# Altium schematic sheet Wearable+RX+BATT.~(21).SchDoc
size A2; PageSetup: Record=PageOptions|CenterHorizontal=True|CenterVertical=True|PrintScale=0.71|XCorrection=1.00|YCorrection=1.00|PrintKind=2|BorderSize=5000000|LeftOffset=0|BottomOffset=0|Orientation=2|PaperLength=1000|PaperWidth=1000|Scale=100|PaperSource=7|PrintQuality=-4|MediaType=1|DitherType=10|PaperKind=A3|PrintScaleMode=1
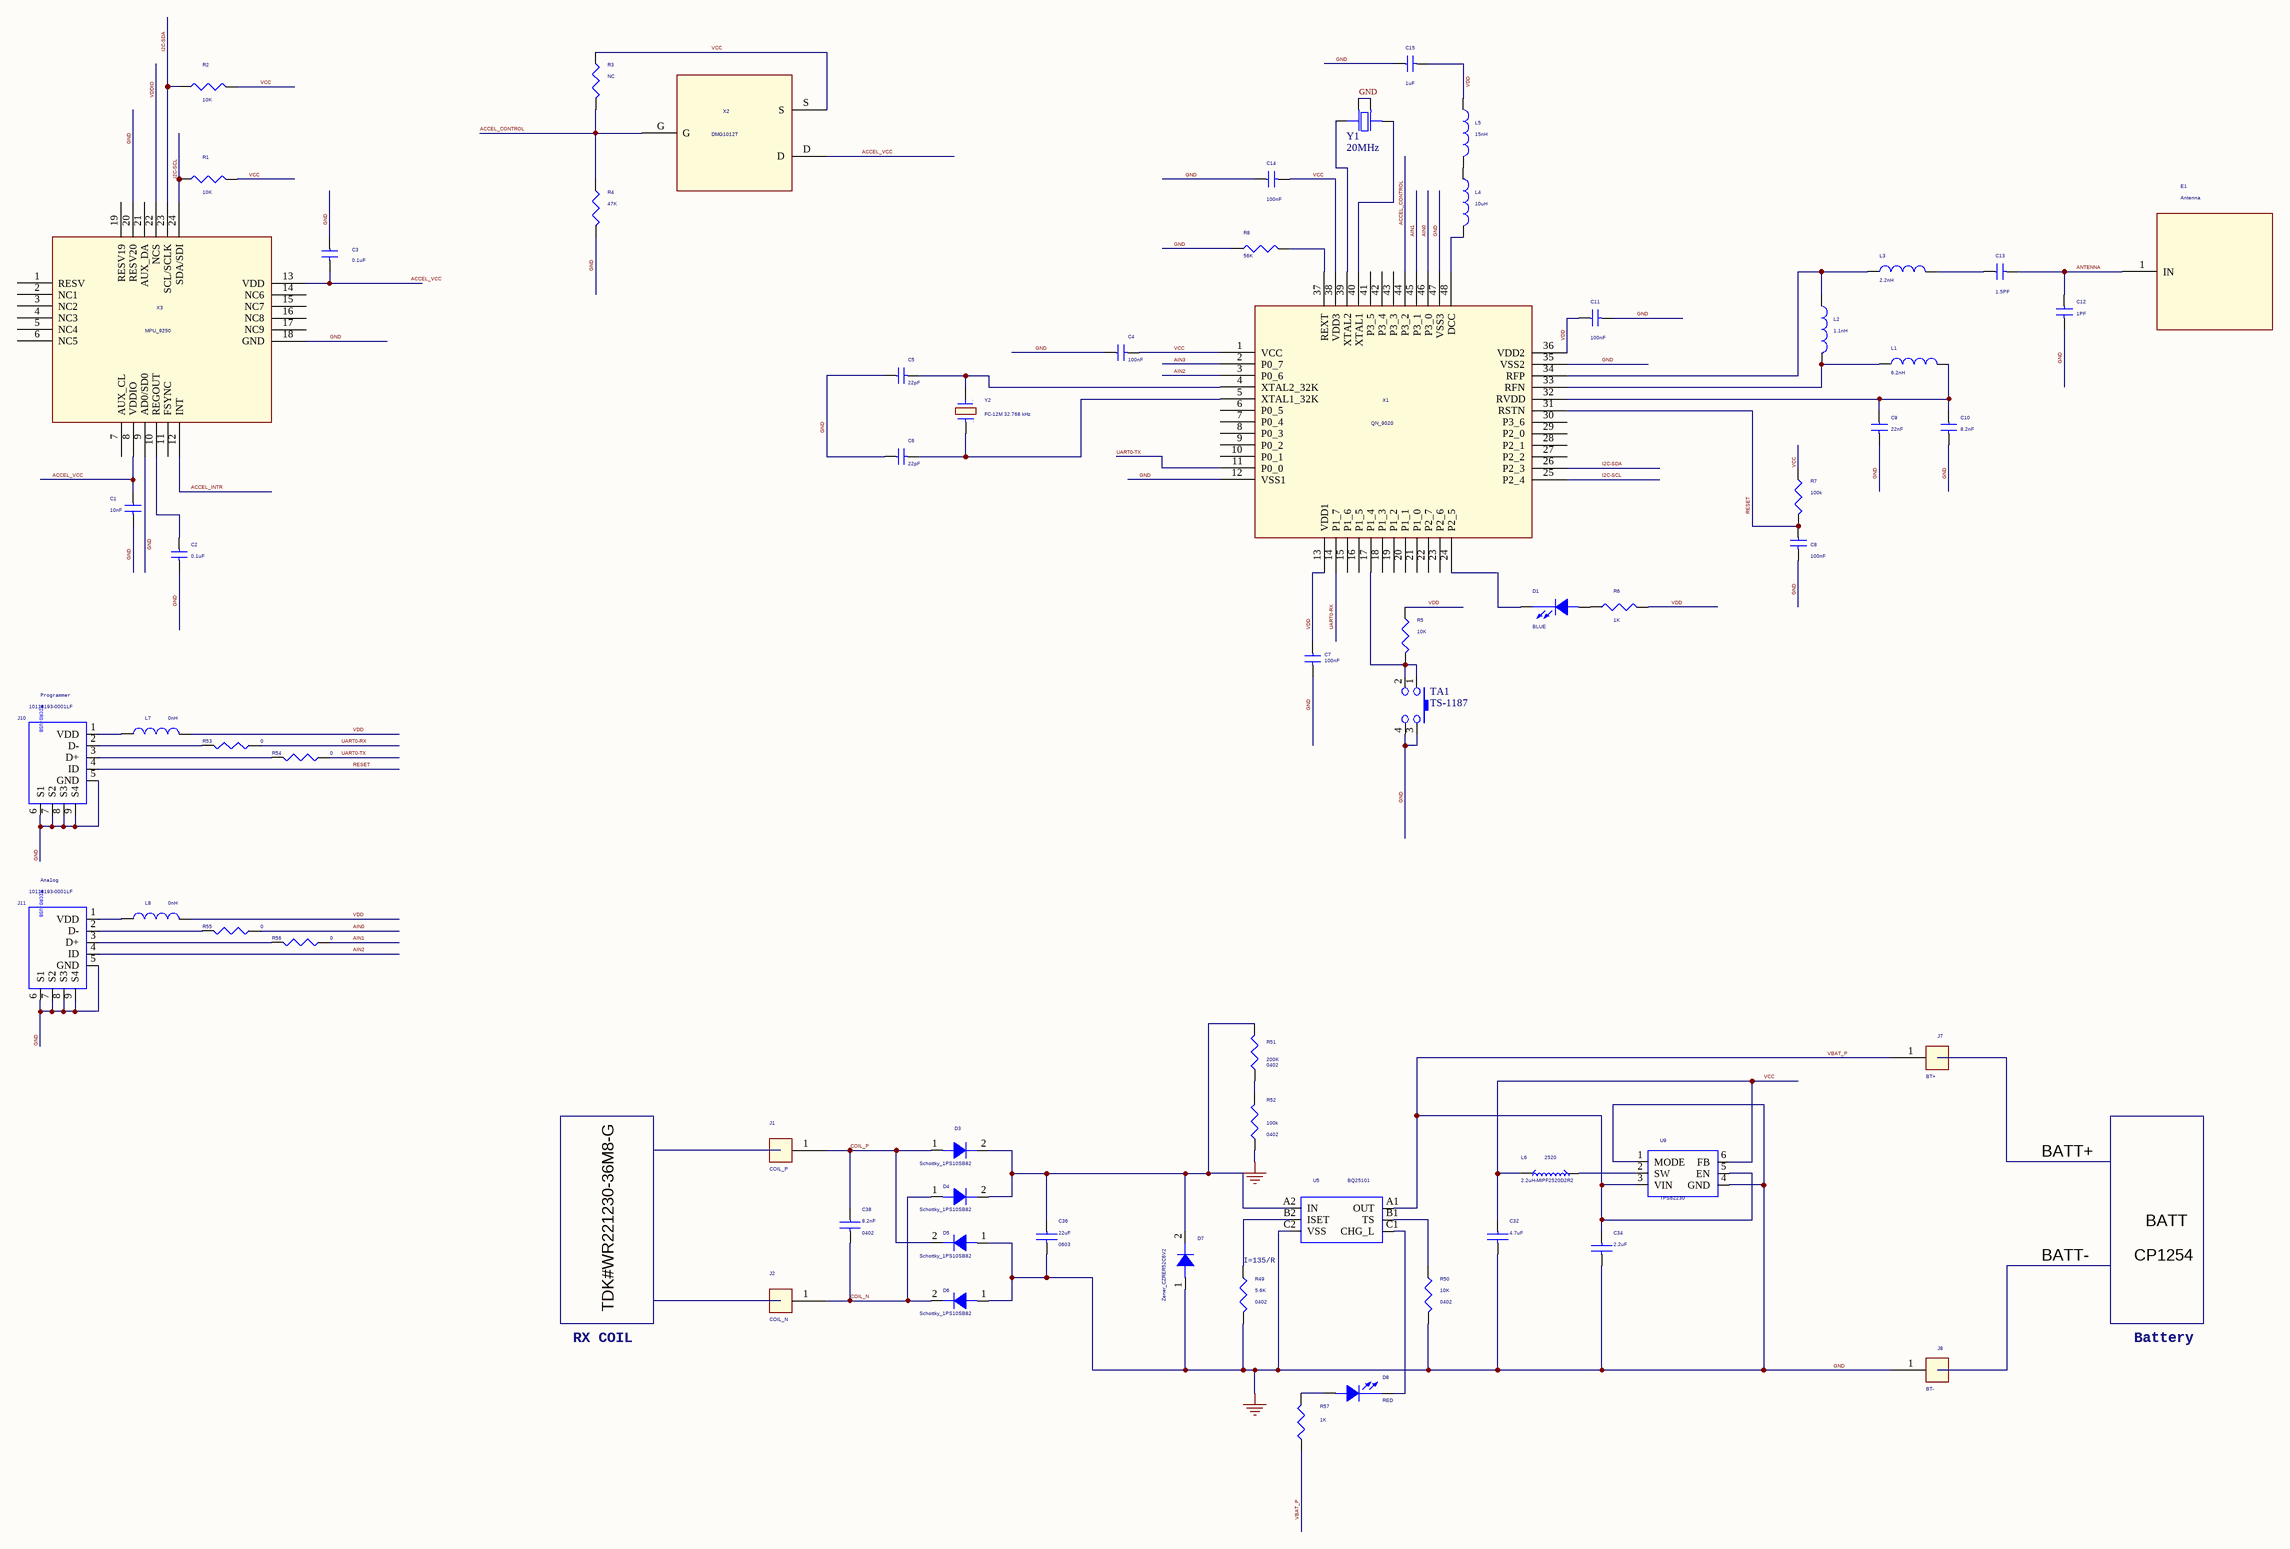
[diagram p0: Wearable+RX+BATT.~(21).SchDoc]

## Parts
C1  10nF  [0402C]
C2  0.1uF  [0402C]
C3  0.1uF  [0402C]
C4  100nF  [0402C]
C5  22pF  [0402C]
C6  22pF  [0402C]
C7  100nF  [0402C]
C8  100nF  [0402C]
C9  22nF  [0402C]
C10  8.2nF  [0402C]
C11  100nF  [0402C]
C12  1PF  [0402C]
C13  1.5PF  [0402C]
C14  100nF  [0402C]
C15  1uF  [0402C]
C32  4.7uF  [0402C]
C34  2.2uF  [0402C]
C36  22uF  Package: 0603  [0603CS]
C38  8.2nF  Package: 0402  [0402C]
D1  BLUE  [0603D]
D3  Schottky_1PS10SB82  [SOD882]
D4  Schottky_1PS10SB82  [SOD882]
D5  Schottky_1PS10SB82  [SOD882]
D6  Schottky_1PS10SB82  [SOD882]
D7  Zener_CZRER52C6V2  [1308D]
D8  RED  [0603D]
E1  Antenna  [3216]
J1  COIL_P  [PAD]
J2  COIL_N  [PAD]
J7  BT+  [PAD]
J8  BT-  [PAD]
J10  10118193-0001LF  [10118193-0001LF]
J11  10118193-0001LF  [10118193-0001LF]
L1  6.2nH  [0402L]
L2  1.1nH  [0402L]
L3  2.2nH  [0402L]
L4  10uH  [0603LS]
L5  15nH  [0402L]
L6  2.2uH-MIPF2520D2R2  [2520]
L7  0nH  [0402L]
L8  0nH  [0402L]
R1  10K  [0402R]
R2  10K  [0402R]
R3  NC  [0402R]
R4  47K  [0402R]
R5  10K  [0402R]
R6  1K  [0402R]
R7  100k  [0402R]
R8  56K  [0402R]
R49  5.6K  PACKAGE: 0402  [0402R]
R50  10K  PACKAGE: 0402  [0402R]
R51  200K  PACKAGE: 0402  [0402R]
R52  100k  PACKAGE: 0402  [0402R]
R53  0  [0402R]
R54  0  [0402R]
R55  0  [0402R]
R56  0  [0402R]
R57  1K  [0402R]
TA1  TS-1187  [TS-1187]
U5  BQ25101  [XBGA-N6-BQ25101]
U9  TPS62230  [USON6-TPS62230]
X1  QN_9020  [Quad48]
X2  DMG1012T  [SOT523]
X3  MPU_9250  [QFN24-MPU9250]
Y1  20MHz  [FA-20H]
Y2  FC-12M 32.768 kHz  [FC-12M]

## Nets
GND: C1.2 C2.2 C3.1 C4.1 C5.1 C6.1 C7.2 C8.2 C9.2 C10.2 C11.2 C12.2 C14.1 C15.1 C32.2 C34.2 C36.2 D5.1(ANODE) D6.1(ANODE) D7.1(ANODE) J8.1 J10.5(GND) J10.6(S1) J10.7(S2) J10.8(S3) J10.9(S4) J11.5(GND) J11.6(S1) J11.7(S2) J11.8(S3) J11.9(S4) R4.2 R8.1 R49.2 R50.2 R52.1 TA1.3 TA1.4 U5.C2(VSS) U9.1(MODE) U9.4(GND) X1.12(VSS1) X1.35(VSS2) X1.47(VSS3) X3.9(AD0/SD0) X3.18(GND) X3.20(RESV20) Y1.2 Y1.4
ACCEL_CONTROL: R3.2 R4.1 X1.44(P3_2) X2.G
ACCEL_INTR: X3.12(INT)
ACCEL_VCC: C1.1 C3.2 X2.D X3.8(VDDIO) X3.13(VDD)
AIN0: R55.1 X1.46(P3_0)
AIN1: R56.1 X1.45(P3_1)
AIN2: J11.4(ID) X1.3(P0_6)
AIN3: X1.2(P0_7)
ANTENNA: C12.1 C13.2 E1.1(IN)
COIL_N: C38.2 D4.1(ANODE) D6.2(CATHODE) J2.1
COIL_P: C38.1 D3.1(ANODE) D5.2(CATHODE) J1.1
I2C-SCL: R1.1 X1.25(P2_4) X3.24(SDA/SDI)
I2C-SDA: R2.1 X1.26(P2_3) X3.23(SCL/SCLK)
RESET: C8.1 J10.4(ID) R7.2 X1.31(RSTN)
UART0-RX: R53.1 X1.14(P1_7)
UART0-TX: R54.1 X1.11(P0_0)
VBAT_P: C34.1 J7.1 R57.1 U5.A1(OUT) U9.3(VIN) U9.5(EN)
VCC: C4.2 C14.2 C32.1 L6.1 R1.2 R2.2 R3.1 R7.1 U9.6(FB) X1.1(VCC) X1.38(VDD3) X2.S
VDD: C7.1 C11.1 C15.2 L5.1 L7.2 L8.2 R5.1 R6.2 X1.13(VDD1) X1.36(VDD2)
VDDIO: X3.22(NCS)
NetC2_1: C2.1 X3.10(REGOUT)
NetC5_2: C5.2 X1.4(XTAL2_32K) Y2.2
NetC6_2: C6.2 X1.5(XTAL1_32K) Y2.1
NetC9_1: C9.1 C10.1 L1.2 X1.32(RVDD)
NetC13_1: C13.1 L3.2
NetC36_1: C36.1 D3.2(CATHODE) D4.2(CATHODE) D7.2(CATHODE) R51.2 U5.A2(IN)
NetD1_1: D1.1(CATHODE) X1.24(P2_5)
NetD1_2: D1.2(ANODE) R6.1
NetD8_1: D8.1(CATHODE) U5.C1(CHG_L)
NetD8_2: D8.2(ANODE) R57.2
NetJ10_1: J10.1(VDD) L7.1
NetJ10_2: J10.2(D-) R53.2
NetJ10_3: J10.3(D+) R54.2
NetJ11_1: J11.1(VDD) L8.1
NetJ11_2: J11.2(D-) R55.2
NetJ11_3: J11.3(D+) R56.2
NetL1_1: L1.1 L2.2 X1.33(RFN)
NetL2_1: L2.1 L3.1 X1.34(RFP)
NetL4_1: L4.1 L5.2
NetL4_2: L4.2 X1.48(DCC)
NetL6_2: L6.2 U9.2(SW)
NetR5_2: R5.2 TA1.1 TA1.2 X1.17(P1_4)
NetR8_2: R8.2 X1.37(REXT)
NetR49_1: R49.1 U5.B2(ISET)
NetR50_1: R50.1 U5.B1(TS)
NetR51_1: R51.1 R52.2
NetX1_39: X1.39(XTAL2) Y1.1
NetX1_40: X1.40(XTAL1) Y1.3

Not connected (* = marked no-connect by the designer): X1 6(P0_5) 7(P0_4) 8(P0_3) 9(P0_2) 10(P0_1) 15(P1_6) 16(P1_5) 18(P1_3) 19(P1_2) 20(P1_1) 21(P1_0) 22(P2_7) 23(P2_6) 27(P2_2) 28(P2_1) 29(P2_0) 30(P3_6) 41(P3_5) 42(P3_4) 43(P3_3); X3 1(RESV) 2(NC1) 3(NC2) 4(NC3) 5(NC4) 6(NC5) 7(AUX_CL) 11(FSYNC) 14(NC6) 15(NC7) 16(NC8) 17(NC9) 19(RESV19) 21(AUX_DA)

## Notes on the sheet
- (near J10) Programmer
- (near J11) Analog
- BATT+
- BATT
- (near R49) I=135/R
- BATT-
- CP1254
- RX COIL
- TDK#WR221230-36M8-G
- Battery

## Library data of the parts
C1-C15 = SMALL CAP
C32 = CAP_CER_4.7uf_0603: GATAN: 13985; Voltage: 25V; Tolerance: 10; MFG#: GRM21BR71E225KA73L; MFG: TDK; DESC: C1005X5R0J475K050BC
C34 = CAP_2.2nF_X7R_0603: Desc: C1005X5R0J225K050BC; GATAN: 100776; MFG: TDK; MFG#: C0603C104M5RACTU; Tolerance: 20; Voltage: 50V
C36 = CAP_2.2nF_X7R_0603: Desc: C1005X5R01J106M050BC; GATAN: 100776; MFG: TDK; MFG#: C0603C104M5RACTU; Tolerance: 20; Voltage: 50V
C38 = CAP_CER_4.7uf_0603: GATAN: 13985; Voltage: 25V; Tolerance: 10; MFG#: GRM21BR71E225KA73L; MFG: AVX; DESC: 0201ZD822KAT2A
D1 D8 = LED
D3-D6 = SchottkyDiode_1PS10SB82: MFG: NXP
D7 = Z_Diode_CZRER52C6V2: MFG: Comchip; DESC: Zener
J1 J2 J7 J8 = CON1: DESC: SOLDER POINT
J10 J11 = 10118193-0001LF_MUSB_1: Number devices in Package: 1; OriginalSymbolOrigin: (0,0); DESC: Micro USB connector; MFG: FCI
L1-L5 L7 L8 = INDUCTOR
L6 = MLZ1005M2R2W_Ind402_0: MFG: FDK; MFG#: CRCW060310K0FKEA; GATAN: 11135; DESC: MIPF2520D4R7
R1 = RESISTOR/SM
R2-R8 R57 = R
R49 = RES_10K_0603_THK_1%: MFG: Panasonic; MFG#: CRCW060310K0FKEA; GATAN: 11135; DESC: ERJ-XGNJ562Y
R50 = RES_10K_0603_THK_1%: MFG: Samsung; MFG#: CRCW060310K0FKEA; GATAN: 11135; DESC: RC0402F103CS
R51-R56 = RES_10K_0603_THK_1%: MFG: Parasonic; MFG#: CRCW060310K0FKEA; GATAN: 11135; DESC: ERJ-1GEF1004C
TA1 = SW-PB 4P_1: TACT SW
U5 = BQ25101_0: OriginalSymbolOrigin: (0,0); Number devices in Package: 1; MFG: TI; DESC: Charger
U9 = TPS62232_6P_SQN: OriginalSymbolOrigin: (0,0); Number devices in Package: 1; DESC: PMIC; MFG: TI
X3 = MPU_1
Y1 = FA-20H
Y2 = QZP100K: PSpiceTemplate: X^@REFDES %1 %2 @MODEL; DESC: Crystal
